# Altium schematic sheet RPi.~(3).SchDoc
size A
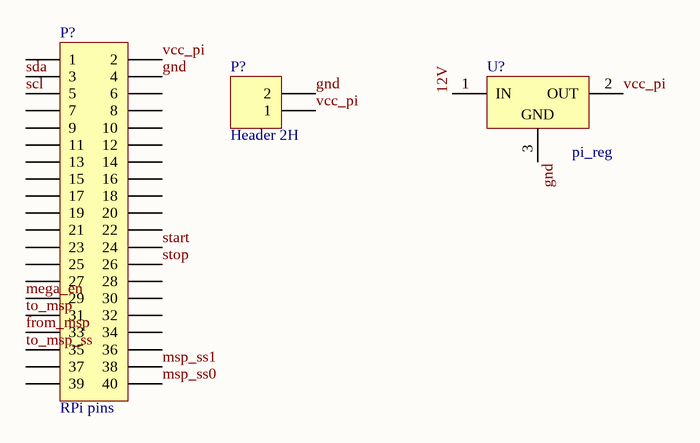
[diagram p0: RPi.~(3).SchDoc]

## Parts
(Parts that share a designator on the sheet are numbered #1, #2 ... from top to bottom, then left to right.)
P?#1  RPi pins  [HDR2X20]
P?#2  Header 2H  [HDR1X2H]
U?  pi_reg  [TO220ABN]

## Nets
12V: U?.1(IN)
from_msp: P?#1.33
gnd: P?#1.4 P?#2.2 U?.3(GND)
mega_en: P?#1.29
msp_ss0: P?#1.40
msp_ss1: P?#1.38
scl: P?#1.5
sda: P?#1.3
start: P?#1.24
stop: P?#1.26
to_msp: P?#1.31
to_msp_ss: P?#1.35
vcc_pi: P?#1.2 P?#2.1 U?.2(OUT)

Not connected (* = marked no-connect by the designer): P?#1 1 6 7 8 9 10 11 12 13 14 15 16 17 18 19 20 21 22 23 25 27 28 30 32 34 36 37 39

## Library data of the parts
P?#1 = Header 20X2: Header, 20-Pin, Dual row
P?#2 = Header 2H: Header, 2-Pin, Right Angle
U? = L7805CV: Positive Voltage Regulator; Note: Tab is connected to pin 3 (GND).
